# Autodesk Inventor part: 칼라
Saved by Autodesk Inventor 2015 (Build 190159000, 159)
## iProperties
Created: 2025-08
Part Number: 칼라
Material: 일반
Document SubType Name: Modeling
Designer: USER
Density: 1 g/cm^3
Appearance: 기본값
Author: USER
Author: jhkim
Creation Date: 2025-08-05
Sending System: Autodesk Inventor 2026
Preprocessor: ST-DEVELOPER v20.1
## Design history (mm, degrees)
node "칼라1"
node "솔리드1"
node "기준1"
